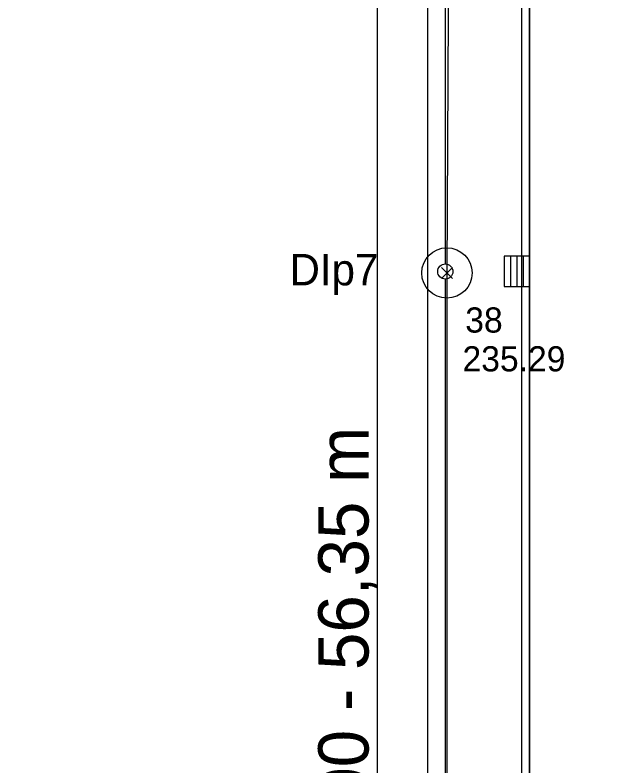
# Model space of a CAD drawing. Extents: x -264234 to -263604, y -1242346 to -1242049.
# Drawn here: x -263832.36 to -263809, y -1242184 to -1242154.19 of the extents above; entities that cross this region are included whole.
import ezdxf

# ---------------------------------------------------------------- set-up
doc = ezdxf.new("R2010")
doc.units = 0
for name, color, linetype in [('KFA_BODY_CISLO', 7, 'Continuous'), ('KFA_BODY_SYMBOL', 7, 'Continuous'), ('KFA_BODY_VYSKA', 7, 'Continuous'), ('KFA_DAZDOVA_KANALIZACIA_vetva_I', 7, 'Continuous'), ('KFA_DAZDOVA_KANALIZACIA_vetva_I_popis', 7, 'Continuous'), ('KFA_SITUACIA_DSP', 7, 'Continuous')]:
    doc.layers.add(name, color=color, linetype=linetype)

msp = doc.modelspace()

# ---------------------------------------------------------------- linework, layer by layer
at = {"layer": 'KFA_BODY_SYMBOL'}
for p, q in [((-263815.419, -1242164.664), (-263814.977, -1242164.222)), ((-263814.977, -1242164.664), (-263815.419, -1242164.222))]:
    msp.add_line(p, q, dxfattribs=at)
at = {"layer": 'KFA_DAZDOVA_KANALIZACIA_vetva_I'}
msp.add_lwpolyline([(-263814.907, -1242107.856), (-263815.198, -1242164.443), (-263815.189, -1242220.791), (-263852.152, -1242220.736), (-263888.701, -1242220.786), (-263906.731, -1242239.259)], dxfattribs=at)
msp.add_circle((-263815.198, -1242164.443), 1, dxfattribs=at)
at = {"layer": 'KFA_SITUACIA_DSP'}
for p, q in [((-263815.263, -1242108.177), (-263815.263, -1242164.087)), ((-263811.918, -1242163.782), (-263812.918, -1242163.782)), ((-263812.918, -1242163.782), (-263812.918, -1242164.982)), ((-263812.668, -1242163.782), (-263812.668, -1242164.982)), ((-263812.418, -1242163.782), (-263812.418, -1242164.982)), ((-263812.168, -1242163.782), (-263812.168, -1242164.982)), ((-263815.263, -1242164.687), (-263815.263, -1242220.396)), ((-263812.918, -1242164.982), (-263811.918, -1242164.982))]:
    msp.add_line(p, q, dxfattribs=at)
for points in [[(-263816.02, -1242224.432), (-263811.918, -1242220.33), (-263811.918, -1242108.434), (-263816.02, -1242104.332), (-263887.916, -1242104.332), (-263892.018, -1242108.434), (-263892.018, -1242147.332), (-263893.618, -1242147.332), (-263893.618, -1242162.382), (-263894.718, -1242162.382), (-263894.718, -1242166.382), (-263893.618, -1242166.382), (-263893.618, -1242181.432), (-263892.018, -1242181.432), (-263892.018, -1242220.33), (-263887.916, -1242224.432)], [(-263816.144, -1242224.132), (-263812.218, -1242220.206), (-263812.218, -1242108.558), (-263816.144, -1242104.632), (-263887.792, -1242104.632), (-263891.718, -1242108.558), (-263891.718, -1242147.632), (-263893.318, -1242147.632), (-263893.318, -1242162.682), (-263894.418, -1242162.682), (-263894.418, -1242166.082), (-263893.318, -1242166.082), (-263893.318, -1242181.132), (-263891.718, -1242181.132), (-263891.718, -1242220.206), (-263887.792, -1242224.132)], [(-263887.968, -1242108.434), (-263815.968, -1242108.434), (-263815.968, -1242220.33), (-263887.968, -1242220.33)], [(-263885.968, -1242111.882), (-263817.968, -1242111.882), (-263817.968, -1242216.882), (-263885.968, -1242216.882)]]:
    msp.add_lwpolyline(points, close=True, dxfattribs=at)
msp.add_lwpolyline([(-263811.918, -1242108.434), (-263811.918, -1242220.33), (-263812.262, -1242220.675), (-263809.862, -1242221.669), (-263810.999, -1242222.806), (-263807.039, -1242226.765), (-263809.585, -1242229.311), (-263813.545, -1242225.351), (-263814.681, -1242226.488), (-263815.675, -1242224.088), (-263816.02, -1242224.432), (-263887.916, -1242224.432), (-263888.26, -1242224.088), (-263889.254, -1242226.488), (-263890.391, -1242225.351), (-263894.351, -1242229.311), (-263896.896, -1242226.765), (-263892.937, -1242222.806), (-263894.073, -1242221.669), (-263891.673, -1242220.675), (-263892.018, -1242220.33), (-263892.018, -1242181.432), (-263893.618, -1242181.432), (-263893.618, -1242147.332)], dxfattribs=at)
msp.add_circle((-263815.263, -1242164.387), 0.3, dxfattribs=at)

# ---------------------------------------------------------------- texts
at = {"layer": 'KFA_BODY_CISLO'}
msp.add_text('38', height=1, dxfattribs=at).set_placement((-263814.47, -1242166.813))
at = {"layer": 'KFA_BODY_VYSKA'}
msp.add_text('235.29', height=1, dxfattribs=at).set_placement((-263814.579, -1242168.355))
at = {"layer": 'KFA_DAZDOVA_KANALIZACIA_vetva_I_popis'}
msp.add_text('DIp7', height=1.25, dxfattribs=at).set_placement((-263821.451, -1242164.937))
msp.add_text('I2, PVC DN300 - 56,35 m', height=2, rotation=90, dxfattribs=at).set_placement((-263818.311, -1242200.884))

doc.saveas('drawing.dxf')
